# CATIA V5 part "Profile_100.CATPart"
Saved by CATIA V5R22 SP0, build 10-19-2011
Part number: Profile_100
Material "Acier": density 7860 kg/m3, Young's modulus 2e+11 Pa, Poisson ratio 0.266, thermal expansion 1.17e-05 1/K
Bounding box of the stored display mesh (mm): x -10 to 10, y -10 to 10, z 0 to 100
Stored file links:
  U:\S9A\PER\CAO\Assemblage\Cadre\Chariot_X\Profile_100.CATPart
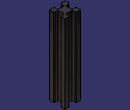
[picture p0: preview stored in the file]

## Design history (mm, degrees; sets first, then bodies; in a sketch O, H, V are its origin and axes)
Body1 (main body), material "Acier"
  Sketch1 on xy-plane, origin (0, 0, 0), H (1, 0, 0), V (0, 1, 0)
    line L1 (10, 10) -> (10, -10)
    line L2 (10, -10) -> (-10, -10)
    line L3 (-10, -10) -> (-10, 10)
    line L4 (-10, 10) -> (10, 10)
    length L2 = 20
    length L1 = 20
    vertical: L1 V, L3 V
    horizontal: L2 H, L4 H
    equidistance: L1 L3 O, L2 L4 O
  Pad1: profile Sketch1, direction (0, 0, 1), length 100
  Sketch2 on end face of Pad1, origin (0, 0, 100), H (1, 0, 0), V (0, 1, 0)
    line L1 (-4, -5) -> (4, -5)
    line L2 (4, -5) -> (4, -10)
    line L3 (4, -10) -> (-4, -10)
    line L4 (-4, -10) -> (-4, -5)
    reference projected line E1 (10, -10) -> (10, 10) from edge [face of Pad1 from Sketch1.L1 | end face of Pad1]
    reference projected line E2 (-10, -10) -> (10, -10) from edge [face of Pad1 from Sketch1.L2 | end face of Pad1]
    length L2 = 5
    length L3 = 8
    distance E1 L2 = 6
    horizontal: L1 H, L3 H
    vertical: L2 V, L4 V
    coincidence: L3 E2
  Pocket1: profile Sketch2, direction (0, 0, -1), length 1000
  CircPattern1: of Pocket1, instances 4, angular step 90, axis from end face of Pad1
  Chamfer1: length 1, angle 45, on edge [face of Pad1 from Sketch1.L1 | face of CircPattern1]; edge [face of CircPattern1 | face of Pad1 from Sketch1.L1]; edge [face of Pad1 from Sketch1.L4 | face of CircPattern1]; edge [face of CircPattern1 | face of Pad1 from Sketch1.L4]; edge [face of Pad1 from Sketch1.L3 | face of CircPattern1]; edge [face of CircPattern1 | face of Pad1 from Sketch1.L3]; edge [face of Pad1 from Sketch1.L2 | face of Pocket1 from Sketch2.L4]; edge [face of Pocket1 from Sketch2.L2 | face of Pad1 from Sketch1.L2]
